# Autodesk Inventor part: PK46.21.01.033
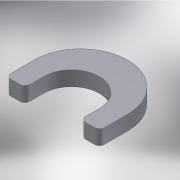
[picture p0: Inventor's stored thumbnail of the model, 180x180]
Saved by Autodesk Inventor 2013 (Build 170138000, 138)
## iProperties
Created: 2005-04
Part Number: PK46.21.01.033
Material: Steel, Mild
Document SubType Name: Modeling
Designer: salex
Manufacturer: Standard
Standards Organization: Custom
Density: 7.86 g/cm^3
Author: salex
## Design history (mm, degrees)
sketch "Эскиз1"
  geometry: L1 (-29.998, 0)-(-29.998, -20); L2 (-29.998, -20)-(-49.998, -20); L3 (-49.998, -20)-(-49.998, 10); L4 (30.002, 0)-(30.002, -20); L5 (30.002, -20)-(50.002, -20); L6 (50.002, -20)-(50.002, 10); A1 r 30 centre (0.002, 0) between (30.002, 0) and (-29.998, 0); A2 r 50 centre (0.002, 10) between (50.002, 10) and (-49.998, 10)
  constraints: 12 end point, 4 point on circle, 4 tangent, 3 parallel, 2 centre point, 2 collinear, 2 perpendicular, 1 vertical, 1 other
  dimensions: "d0" = 10 distance of A1.centre A2.centre; "d1" = 20 distance from line of A1.centre L2; "d2" = 30 radius of A1; "d3" = 50 radius of A2
extrude "Выдавливание1" new body sketch "Эскиз1" distance "d4" = 16; taper "d5" = 0 deg
fillet "Сопряжение1" dims "d6" = 5
body "Solid1"
